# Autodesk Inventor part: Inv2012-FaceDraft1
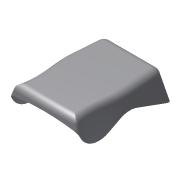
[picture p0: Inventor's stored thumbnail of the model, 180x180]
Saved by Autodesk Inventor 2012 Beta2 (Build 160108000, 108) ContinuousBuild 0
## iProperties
Created: 2011-02
Part Number: Inv2012-FaceDraft1
Material: Default
Document SubType Name: Modeling
Designer: ehttln
Density: 1 g/cm^3
Author: ehttln
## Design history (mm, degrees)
sketch "Sketch1"
  geometry: L1 (-23.559, -52.24)-(26.441, -52.24); L2 (26.441, -52.24)-(26.441, 17.76); L3 (26.441, 17.76)-(-23.559, 17.76); L4 (-23.559, 17.76)-(-23.559, -52.24); 1 further point
  constraints: 8 end point, 2 parallel, 1 horizontal, 1 perpendicular
  dimensions: "d0" = 50 distance of L2.end L3.end; "d1" = 70 distance of L3.end L1.start
extrude "Extrusion1" new body sketch "Sketch1" distance "d2" = 27.5; taper "d3" = 0 deg
fillet "Fillet6" dims "d55" = 5
sketch "Sketch2"
  geometry: L1 (0, 0)-(-27.5, 0) reference; L2 (0, 0)-(0, 70) reference; L3 (0, 70)-(-27.5, 70) reference; L4 (-27.5, 70)-(-27.5, 0) reference; L5 (-5, 70)-(-14.595, 43.637); L6 (-13.807, 31.585)-(-9.193, 22.713); L7 (-15.173, 2.702)-(-20, 0); A1 r 15 centre (-0.5, 38.507) between (-14.595, 43.637) and (-13.807, 31.585); A2 r 15 centre (-22.5, 15.791) between (-15.173, 2.702) and (-9.193, 22.713); 1 further point
  constraints: 6 end point, 4 point on circle, 4 tangent, 2 centre point, 2 point on line
  dimensions: "d24" = 5 distance from line of L2 L5.start; "d31" = 20 distance of L1.start L7.end; "d33" = 110 deg angle of L3 L5; "d34" = 15 radius of A1; "d35" = 15 radius of A2; "d36" = 10 distance of L6.start L6.end; "d37" = 5 distance from line of L4 A2.centre; "d39" = 22 horizontal distance of A1.centre A2.centre
feature "FaceDraft6" sketch "Sketch2" dims angle "d42" = 12 deg, "d43" = 3 deg
sketch "Sketch6"
  geometry: L1 (13.807, 31.585)-(9.193, 22.713) reference; L2 (15.173, 2.702)-(20, 0) reference; L3 (5, 70)-(14.595, 43.637) reference; A1 r 15 centre (0.5, 38.507) between (13.807, 31.585) and (14.595, 43.637) reference; A2 r 15 centre (22.5, 15.791) between (9.193, 22.713) and (15.173, 2.702) reference; 1 further point
feature "FaceDraft7" sketch "Sketch6" dims angle "d44" = 12 deg, "d45" = 3 deg
sketch "Sketch7"
  geometry: A1 r 150 centre (23.952, -127.902) between (48.952, 20) and (-1.048, 20); 1 further point
  constraints: 2 point on circle, 1 centre point
  dimensions: "d46" = 150 radius of A1
feature "FaceDraft8" sketch "Sketch7" dims angle "d47" = 12 deg, "d48" = 3 deg
sketch "Sketch8"
  geometry: L1 (49.476, 0)-(0, 0) reference; L2 (-0.262, -5)-(49.738, -5); 1 further point
  constraints: 2 end point, 1 parallel
feature "FaceDraft9" sketch "Sketch8" dims angle "d50" = 12 deg
delete_face "Delete Face2"
fillet "Fillet5" dims "d52" = 5, "d53" = 2
body "Solid1"
